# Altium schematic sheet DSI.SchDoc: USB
size A4; Author: Daniela Catanzaro; CompanyName: Arduino srl; DocumentNumber: ASX00055; SheetNumber: 10; SheetTotal: 10; RevAuthor: Daniela Catanzaro
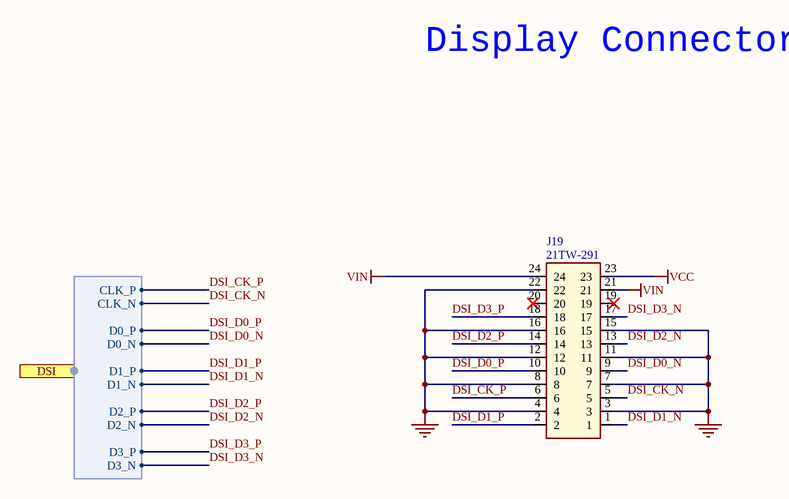
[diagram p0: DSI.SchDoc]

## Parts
J19  21TW-291  [21TW-291]

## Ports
DSI (harness DISPLAY)

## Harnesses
DISPLAY: CLK_N, CLK_P, D0_N, D0_P, D1_N, D1_P, D2_N, D2_P, D3_N, D3_P

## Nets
GND: J19.3 J19.4 J19.7 J19.8 J19.11 J19.12 J19.15 J19.16 J19.22
VCC: J19.23
VIN: J19.21 J19.24
DSI_CK_N: J19.5 ; port DSI.CLK_N
DSI_CK_P: J19.6 ; port DSI.CLK_P
DSI_D0_N: J19.9 ; port DSI.D0_N
DSI_D0_P: J19.10 ; port DSI.D0_P
DSI_D1_N: J19.1 ; port DSI.D1_N
DSI_D1_P: J19.2 ; port DSI.D1_P
DSI_D2_N: J19.13 ; port DSI.D2_N
DSI_D2_P: J19.14 ; port DSI.D2_P
DSI_D3_N: J19.17 ; port DSI.D3_N
DSI_D3_P: J19.18 ; port DSI.D3_P

Not connected (* = marked no-connect by the designer): J19 19* 20*

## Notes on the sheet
- Display Connector

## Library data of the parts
J19 = J0265-A.9: CONN SOCKET 2ROW 24POS VERTICAL PASS THROUGH + SMD with fixing + reel + cap for pick and place; Manufacturer: 4UCON; Connector Type: BOARD CONNECTOR; Code Arduino: J0265; Number of Contacts: 24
